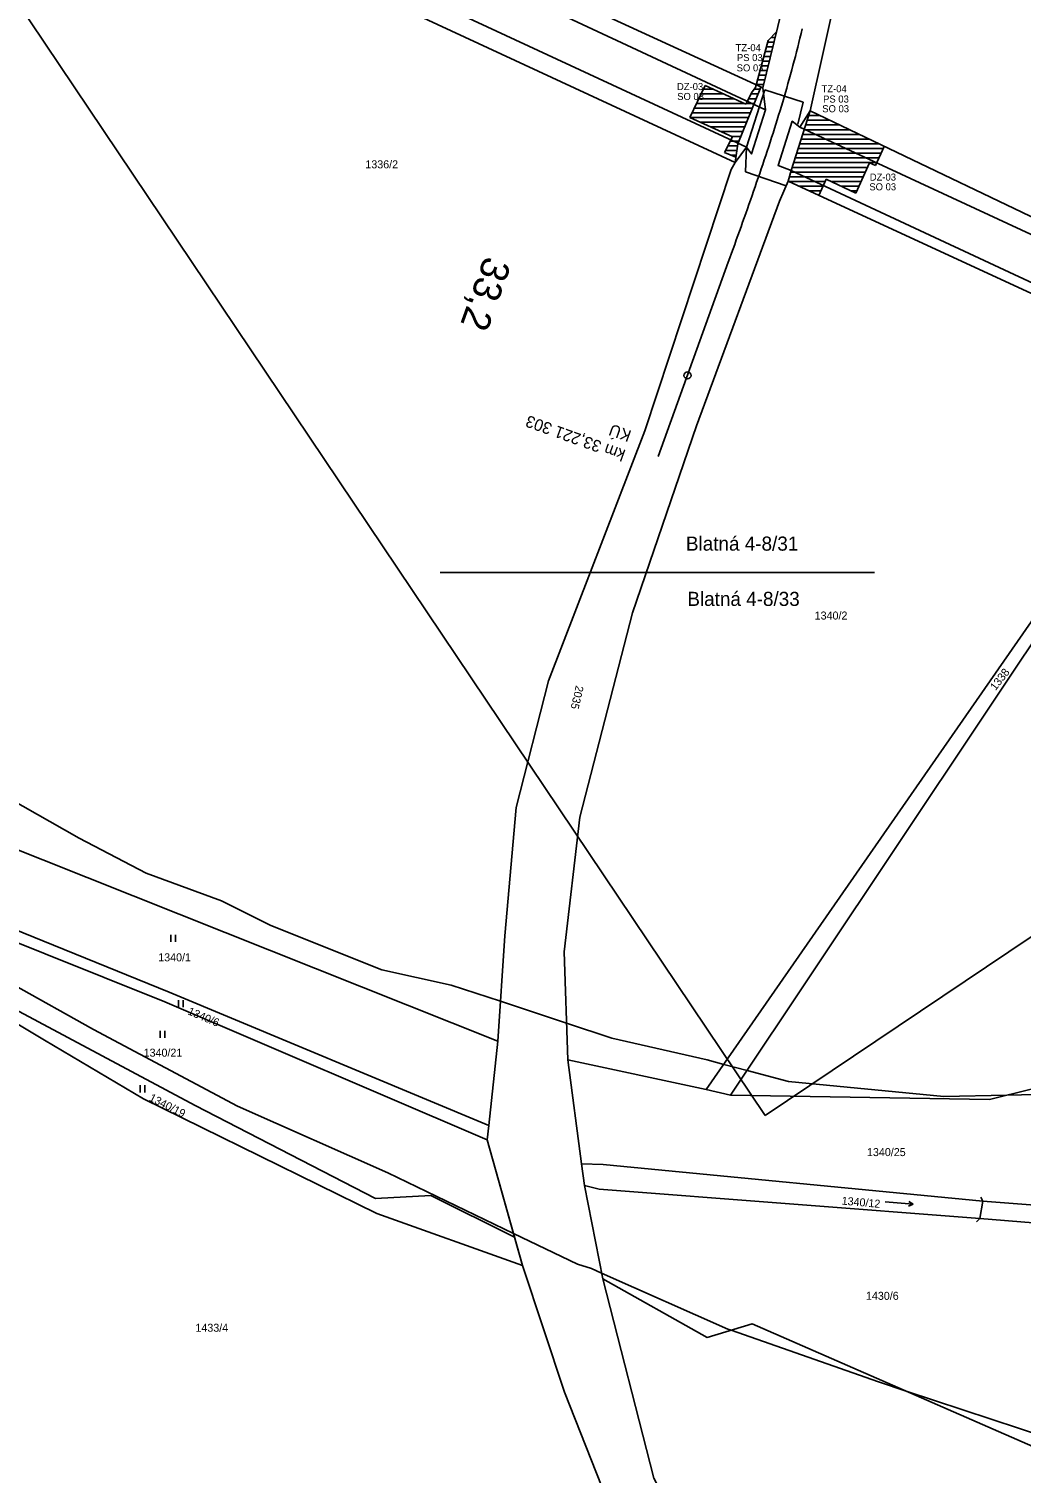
# Model space of a CAD drawing. Extents: x -794765 to -785424, y -1118958 to -1108731.
# Drawn here: x -787414.2 to -787203.5, y -1117691.3 to -1117384.5 of the extents above; entities that cross this region are included whole.
import ezdxf

# ---------------------------------------------------------------- set-up
doc = ezdxf.new("R2010")
doc.units = 0
for name, color, linetype in [('Level 66', 7, 'Continuous'), ('Level 71', 7, 'Continuous'), ('Level 73', 7, 'Continuous'), ('Level 75', 7, 'Continuous'), ('Level 76', 7, 'Continuous'), ('Level 77', 7, 'Continuous'), ('Level 81', 7, 'Continuous'), ('Vrstva 1', 7, 'Continuous'), ('Vrstva 53', 7, 'Continuous')]:
    doc.layers.add(name, color=color, linetype=linetype)

msp = doc.modelspace()

# ---------------------------------------------------------------- linework, layer by layer
at = {"layer": 'Level 66'}
for p, q in [((-787384.07, -1117578.45), (-787384.07, -1117576.95)), ((-787383.07, -1117578.45), (-787383.07, -1117576.95)), ((-787382.44, -1117592.34), (-787382.44, -1117590.84)), ((-787381.44, -1117592.34), (-787381.44, -1117590.84)), ((-787386.34, -1117598.85), (-787386.34, -1117597.35)), ((-787385.34, -1117598.85), (-787385.34, -1117597.35)), ((-787390.57, -1117610.42), (-787390.57, -1117608.92)), ((-787389.57, -1117610.42), (-787389.57, -1117608.92)), ((-787232.37, -1117633.68), (-787226.4, -1117634.2)), ((-787226.4, -1117634.2), (-787227.33, -1117633.62)), ((-787226.4, -1117634.2), (-787227.41, -1117634.62))]:
    msp.add_line(p, q, dxfattribs=at)
at = {"layer": 'Level 71'}
msp.add_line((-787257.85, -1117615.31), (-787008.17, -1117447.61), dxfattribs=at)
msp.add_lwpolyline([(-787008.17, -1117447.61), (-787479.8, -1116745.45), (-787729.47, -1116913.15), (-787257.85, -1117615.31)], dxfattribs=at)
at = {"layer": 'Level 75'}
for p, q in [((-787258.37, -1117397.06), (-787413.22, -1117325.67)), ((-787264.26, -1117412.91), (-787413.04, -1117343.78)), ((-787438.47, -1117550.22), (-787314.62, -1117599.54)), ((-787316.54, -1117617.47), (-787314.62, -1117599.54)), ((-787299.73, -1117603.52), (-787270.37, -1117609.83)), ((-787296.84, -1117625.58), (-787299.73, -1117603.52)), ((-787270.37, -1117609.83), (-787265.2, -1117611.01)), ((-787316.9, -1117620.47), (-787316.54, -1117617.47)), ((-787316.9, -1117620.47), (-787311.06, -1117641.19)), ((-787296.23, -1117630.19), (-787296.84, -1117625.58)), ((-787292.35, -1117650.03), (-787296.23, -1117630.19)), ((-787311.06, -1117641.19), (-787309.36, -1117647.22))]:
    msp.add_line(p, q, dxfattribs=at)
for points in [[(-787248.32, -1117401.92), (-787242.61, -1117376.43), (-787241.48, -1117360.62), (-787238.86, -1117328.3), (-787240.18, -1117309.09), (-787244.19, -1117287.3), (-787255.58, -1117252.15), (-787259.63, -1117245.84), (-787277.47, -1117212.02), (-787300.85, -1117181.82), (-787327.03, -1117156.98), (-787352.43, -1117134.69)], [(-787356.33, -1117146.67), (-787322.75, -1117175.25), (-787307.2, -1117190.47), (-787292.44, -1117206.89), (-787276.75, -1117230.94), (-787266.99, -1117249.13), (-787259.39, -1117269.6), (-787255.71, -1117285.12), (-787252.03, -1117308.63), (-787250.41, -1117335.48), (-787250.96, -1117360.68), (-787254.36, -1117380.85), (-787258.37, -1117397.06)], [(-787264.26, -1117412.91), (-787261.83, -1117409.67), (-787260.78, -1117411.06), (-787257.76, -1117401.7), (-787258.37, -1117397.06)], [(-787248.32, -1117401.92), (-787250.51, -1117405.41), (-787252.11, -1117404.13), (-787255.1, -1117413.5), (-787252.33, -1117414.61), (-787252.97, -1117416.89)], [(-786706.11, -1117656.27), (-786875.36, -1117577.21), (-787053.8, -1117493.01), (-787183.24, -1117433.1), (-787248.32, -1117401.92)], [(-787314.62, -1117599.54), (-787313.18, -1117577.14), (-787310.72, -1117549.93), (-787303.89, -1117523.03), (-787283.43, -1117469.91), (-787265.1, -1117414.39), (-787264.26, -1117412.91)], [(-787252.97, -1117416.89), (-787254.84, -1117421.14), (-787272.47, -1117468.81), (-787286.03, -1117508.52), (-787297.19, -1117551.99), (-787300.57, -1117580.56), (-787299.73, -1117603.52)], [(-787181.08, -1117450.22), (-787189.33, -1117446.27), (-787252.97, -1117416.89)], [(-787270.37, -1117609.83), (-787195.54, -1117502.09), (-787181.08, -1117450.22)], [(-787265.2, -1117611.01), (-787193.72, -1117503.85), (-787178.49, -1117451.46)], [(-787460.09, -1117558.43), (-787384.46, -1117589.14), (-787316.54, -1117617.47)], [(-787462, -1117560.43), (-787385.34, -1117591.22), (-787316.9, -1117620.47)], [(-787311.06, -1117641.19), (-787328.89, -1117632.33), (-787340.58, -1117632.95), (-787378.91, -1117613.22), (-787459.04, -1117570.42)], [(-787459.04, -1117570.42), (-787410.93, -1117599.34), (-787389.9, -1117611.79), (-787340.35, -1117636.15), (-787309.36, -1117647.22)], [(-787265.2, -1117611.01), (-787210.23, -1117611.92), (-787173.69, -1117602.87)], [(-787181.14, -1117636.92), (-787190.01, -1117635.11), (-787200.57, -1117634.38), (-787211.61, -1117633.55), (-787292.23, -1117625.71), (-787296.84, -1117625.58)], [(-787296.23, -1117630.19), (-787293.12, -1117630.97), (-787212.29, -1117637.24), (-787200.96, -1117638.15), (-787190.55, -1117639.98), (-787182.24, -1117641.97)], [(-787309.36, -1117647.22), (-787300.47, -1117674.13), (-787291.42, -1117697.04), (-787259.05, -1117754.75), (-787242.15, -1117783.25)], [(-787192.6, -1117689.33), (-787260.59, -1117659.56), (-787270.16, -1117662.49), (-787292.35, -1117650.03)], [(-787208.31, -1117817.12), (-787233.24, -1117774.71), (-787264.39, -1117724.76), (-787281.5, -1117692.34), (-787292.35, -1117650.03)]]:
    msp.add_lwpolyline(points, dxfattribs=at)
at = {"layer": 'Level 77'}
for p, q in [((-787464.41, -1117305.26), (-787257.76, -1117401.7)), ((-787261.83, -1117409.67), (-787410.13, -1117340.66)), ((-787250.51, -1117405.41), (-787184.71, -1117435.94)), ((-787188.65, -1117444.27), (-787252.33, -1117414.61)), ((-787212.29, -1117637.24), (-787211.61, -1117633.55)), ((-787212.06, -1117632.66), (-787211.61, -1117633.55)), ((-787213, -1117637.95), (-787212.29, -1117637.24))]:
    msp.add_line(p, q, dxfattribs=at)
at = {"layer": 'Level 81'}
for points in [[(-787191.1, -1117610.63), (-787206.5, -1117611), (-787219.92, -1117611.31), (-787252.91, -1117608.11), (-787261.71, -1117605.78), (-787266.65, -1117604.47), (-787270.19, -1117603.53), (-787290.43, -1117598.89), (-787300.02, -1117595.72), (-787314.08, -1117591.07), (-787324.53, -1117587.62), (-787339.3, -1117584.36), (-787362.84, -1117575), (-787373.33, -1117569.71), (-787389.32, -1117563.89), (-787403.58, -1117556.41), (-787433.76, -1117539.31), (-787444.38, -1117525.57), (-787452.36, -1117515.25), (-787457.68, -1117504.99), (-787461.95, -1117499.22), (-787461.95, -1117499.22)], [(-787417.72, -1117587.42), (-787400.54, -1117597.07), (-787369.92, -1117613.34), (-787338, -1117627.53), (-787311.28, -1117640.41), (-787297.7, -1117646.95), (-787294.75, -1117647.86), (-787292.59, -1117648.82), (-787265.76, -1117660.71), (-787265.1, -1117660.94), (-787233.78, -1117671.93), (-787227.93, -1117673.86), (-787191.82, -1117685.76), (-787190, -1117686.35), (-787180.34, -1117690.78), (-787169.78, -1117695.08)]]:
    msp.add_lwpolyline(points, dxfattribs=at)
at = {"layer": 'Vrstva 1'}
for p, q in [((-787255.42, -1117385.12), (-787257.23, -1117386.98)), ((-787255.63, -1117385.34), (-787255.47, -1117385.34)), ((-787257.23, -1117386.98), (-787259.93, -1117396.93)), ((-787257.6, -1117388.34), (-787256.21, -1117388.34)), ((-787257.33, -1117387.34), (-787255.96, -1117387.34)), ((-787256.6, -1117386.34), (-787255.72, -1117386.34)), ((-787258.41, -1117391.34), (-787256.95, -1117391.34)), ((-787258.14, -1117390.34), (-787256.71, -1117390.34)), ((-787257.87, -1117389.34), (-787256.46, -1117389.34)), ((-787259.23, -1117394.34), (-787257.7, -1117394.34)), ((-787258.95, -1117393.34), (-787257.45, -1117393.34)), ((-787258.68, -1117392.34), (-787257.2, -1117392.34)), ((-787270.59, -1117396.5), (-787273.84, -1117403.34)), ((-787270.98, -1117397.34), (-787268.79, -1117397.34)), ((-787270.59, -1117396.5), (-787261.95, -1117400.53)), ((-787261.83, -1117409.67), (-787257.92, -1117397.49)), ((-787261.83, -1117409.67), (-787257.92, -1117397.49)), ((-787259.93, -1117396.93), (-787260.58, -1117397.91)), ((-787260.2, -1117397.34), (-787258.96, -1117397.34)), ((-787259.77, -1117396.34), (-787258.19, -1117396.34)), ((-787259.5, -1117395.34), (-787257.94, -1117395.34)), ((-787257.76, -1117401.7), (-787258.37, -1117397.06)), ((-787257.92, -1117397.49), (-787249.76, -1117400.11)), ((-787257.92, -1117397.49), (-787249.76, -1117400.11)), ((-787272.41, -1117400.34), (-787262.36, -1117400.34)), ((-787271.93, -1117399.34), (-787264.5, -1117399.34)), ((-787271.46, -1117398.34), (-787266.65, -1117398.34)), ((-787260.58, -1117397.91), (-787261.95, -1117400.53)), ((-787261.85, -1117400.34), (-787260.17, -1117400.34)), ((-787261.33, -1117399.34), (-787259.77, -1117399.34)), ((-787260.8, -1117398.34), (-787259.36, -1117398.34)), ((-787249.76, -1117400.11), (-787250.89, -1117404.74)), ((-787249.76, -1117400.11), (-787250.89, -1117404.74)), ((-787273.84, -1117403.34), (-787264.78, -1117407.46)), ((-787273.84, -1117403.34), (-787261.38, -1117403.34)), ((-787273.36, -1117402.34), (-787260.98, -1117402.34)), ((-787272.89, -1117401.34), (-787260.58, -1117401.34)), ((-787248.32, -1117401.92), (-787252.33, -1117414.61)), ((-787248.63, -1117402.92), (-787246.23, -1117402.92)), ((-787271.64, -1117404.34), (-787261.79, -1117404.34)), ((-787269.44, -1117405.34), (-787262.19, -1117405.34)), ((-787267.24, -1117406.34), (-787262.6, -1117406.34)), ((-787249.56, -1117405.92), (-787239.97, -1117405.92)), ((-787249.25, -1117404.92), (-787242.06, -1117404.92)), ((-787248.94, -1117403.92), (-787244.15, -1117403.92)), ((-787264.78, -1117407.46), (-787266.5, -1117410.74)), ((-787265.76, -1117409.34), (-787263.71, -1117409.34)), ((-787265.24, -1117408.34), (-787263.4, -1117408.34)), ((-787265.04, -1117407.34), (-787263, -1117407.34)), ((-787262, -1117414.84), (-787261.83, -1117409.67)), ((-787262, -1117414.84), (-787261.83, -1117409.67)), ((-787250.49, -1117408.92), (-787233.71, -1117408.92)), ((-787250.18, -1117407.92), (-787235.8, -1117407.92)), ((-787249.87, -1117406.92), (-787237.88, -1117406.92)), ((-787234.39, -1117413.52), (-787232.58, -1117409.46)), ((-787266.5, -1117410.74), (-787264.09, -1117411.76)), ((-787266.29, -1117410.34), (-787263.87, -1117410.34)), ((-787265.09, -1117411.34), (-787264.02, -1117411.34)), ((-787254.68, -1117412.21), (-787254.68, -1117412.18)), ((-787251.74, -1117412.92), (-787234.12, -1117412.92)), ((-787251.43, -1117411.92), (-787233.68, -1117411.92)), ((-787251.12, -1117410.92), (-787233.23, -1117410.92)), ((-787250.8, -1117409.92), (-787232.78, -1117409.92)), ((-787238.6, -1117419.4), (-787235.68, -1117412.93)), ((-787235.68, -1117412.93), (-787234.39, -1117413.52)), ((-787253.41, -1117417.88), (-787262, -1117414.84)), ((-787252.67, -1117415.92), (-787237.03, -1117415.92)), ((-787252.36, -1117414.92), (-787236.58, -1117414.92)), ((-787252.05, -1117413.92), (-787236.13, -1117413.92)), ((-787252.9, -1117416.92), (-787245.12, -1117416.92)), ((-787250.74, -1117417.92), (-787245.58, -1117417.92)), ((-787248.57, -1117418.92), (-787246.05, -1117418.92)), ((-787246.49, -1117419.88), (-787244.91, -1117416.46)), ((-787238.6, -1117419.4), (-787244.91, -1117416.46)), ((-787243.93, -1117416.92), (-787237.48, -1117416.92)), ((-787241.78, -1117417.92), (-787237.93, -1117417.92)), ((-787239.63, -1117418.92), (-787238.39, -1117418.92)), ((-787265.68, -1117434.06), (-787280.56, -1117475.36)), ((-787326.9, -1117500), (-787234.64, -1117500))]:
    msp.add_line(p, q, dxfattribs=at)
for points in [[(-787265.68, -1117434.06), (-787265.34, -1117433.12), (-787265, -1117432.18), (-787264.66, -1117431.24), (-787264.32, -1117430.3), (-787263.99, -1117429.35), (-787263.65, -1117428.41), (-787263.31, -1117427.47), (-787262.98, -1117426.53), (-787262.64, -1117425.59), (-787262.3, -1117424.65), (-787261.97, -1117423.7), (-787261.64, -1117422.76), (-787261.3, -1117421.82), (-787260.97, -1117420.87), (-787260.64, -1117419.93), (-787260.31, -1117418.99), (-787259.99, -1117418.04), (-787259.66, -1117417.1), (-787259.33, -1117416.15), (-787259.01, -1117415.2), (-787258.69, -1117414.26), (-787258.37, -1117413.31), (-787258.05, -1117412.36), (-787257.74, -1117411.41), (-787257.42, -1117410.46), (-787257.11, -1117409.51), (-787256.8, -1117408.56), (-787256.49, -1117407.61), (-787256.19, -1117406.66), (-787255.89, -1117405.7), (-787255.58, -1117404.75), (-787255.29, -1117403.8), (-787254.99, -1117402.84), (-787254.7, -1117401.88), (-787254.41, -1117400.93), (-787254.12, -1117399.97), (-787253.84, -1117399.01), (-787253.56, -1117398.05), (-787253.28, -1117397.09), (-787253.01, -1117396.13), (-787252.74, -1117395.16), (-787252.47, -1117394.2), (-787252.21, -1117393.24), (-787251.95, -1117392.27), (-787251.69, -1117391.3), (-787251.44, -1117390.34), (-787251.19, -1117389.37), (-787250.95, -1117388.4), (-787250.71, -1117387.43), (-787250.47, -1117386.46), (-787250.24, -1117385.48), (-787250.01, -1117384.51)], [(-787264.26, -1117412.91), (-787261.83, -1117409.67), (-787260.78, -1117411.06), (-787257.76, -1117401.7), (-787258.37, -1117397.06)]]:
    msp.add_lwpolyline(points, dxfattribs=at)
for points in [[(-787264.26, -1117412.91), (-787263.65, -1117408.95), (-787258.77, -1117396.88), (-787258.37, -1117397.06), (-787257.76, -1117401.7), (-787260.78, -1117411.06), (-787261.83, -1117409.67)], [(-787248.32, -1117401.92), (-787252.33, -1117414.61), (-787255.1, -1117413.5), (-787252.11, -1117404.13), (-787250.51, -1117405.41)]]:
    msp.add_lwpolyline(points, close=True, dxfattribs=at)
msp.add_circle((-787274.35, -1117458.12), 0.75, dxfattribs=at)
at = {"layer": 'Vrstva 53'}
for points in [[(-787458.26, -1117042.74), (-787398.26, -1117093.36), (-787375.17, -1117114.73), (-787356.91, -1117130.76), (-787352.43, -1117134.69), (-787327.03, -1117156.98), (-787300.85, -1117181.82), (-787277.47, -1117212.02), (-787259.63, -1117245.84), (-787255.58, -1117252.15), (-787244.19, -1117287.3), (-787240.18, -1117309.09), (-787238.86, -1117328.3), (-787241.48, -1117360.62), (-787242.61, -1117376.43), (-787248.32, -1117401.92), (-787250.51, -1117405.41), (-787252.11, -1117404.13), (-787255.1, -1117413.5), (-787252.33, -1117414.61), (-787252.97, -1117416.89), (-787254.84, -1117421.14), (-787272.47, -1117468.81)], [(-787283.43, -1117469.91), (-787265.1, -1117414.39), (-787264.26, -1117412.91), (-787261.83, -1117409.67), (-787260.78, -1117411.06), (-787257.76, -1117401.7), (-787258.37, -1117397.06), (-787254.36, -1117380.85), (-787250.96, -1117360.68), (-787250.41, -1117335.48), (-787252.03, -1117308.63), (-787255.71, -1117285.12), (-787259.39, -1117269.6), (-787266.99, -1117249.13), (-787276.75, -1117230.94), (-787292.44, -1117206.89), (-787307.2, -1117190.47), (-787322.75, -1117175.25), (-787356.33, -1117146.67), (-787360.49, -1117143.13), (-787390.97, -1117117.19), (-787466.48, -1117052.03)], [(-787145.72, -1117945.71), (-787157.56, -1117922.69), (-787175.04, -1117894.4), (-787191.61, -1117867.54), (-787217.39, -1117821.69), (-787221.52, -1117814.46), (-787228.62, -1117803.68), (-787238.02, -1117789.4), (-787242.15, -1117783.25), (-787259.05, -1117754.75), (-787291.42, -1117697.04), (-787300.47, -1117674.13), (-787309.36, -1117647.22), (-787316.9, -1117620.47), (-787316.54, -1117617.47), (-787314.62, -1117599.54), (-787313.18, -1117577.14), (-787310.72, -1117549.93), (-787303.89, -1117523.03), (-787283.43, -1117469.91)], [(-787272.47, -1117468.81), (-787286.03, -1117508.52), (-787297.19, -1117551.99), (-787300.57, -1117580.56), (-787299.73, -1117603.52), (-787296.84, -1117625.58), (-787296.23, -1117630.19), (-787292.35, -1117650.03), (-787281.5, -1117692.34), (-787264.39, -1117724.76), (-787233.24, -1117774.71), (-787208.31, -1117817.12), (-787200.76, -1117830.15), (-787163.99, -1117893.46), (-787154.27, -1117910.76), (-787140.05, -1117937.14), (-787131.85, -1117955.61)]]:
    msp.add_lwpolyline(points, dxfattribs=at)

# ---------------------------------------------------------------- texts
at = {"layer": 'Level 73'}
msp.add_text('33,2', height=6, rotation=250.1954, dxfattribs=at).set_placement((-787317.37, -1117432.52))
at = {"layer": 'Level 76'}
for s, p in [('1336/2', (-787342.77, -1117414.13)), ('1340/2', (-787247.34, -1117509.98)), ('1340/1', (-787386.76, -1117582.59)), ('1340/21', (-787389.86, -1117602.84)), ('1340/25', (-787236.23, -1117623.96)), ('1430/6', (-787236.45, -1117654.49)), ('1433/4', (-787378.86, -1117661.27))]:
    msp.add_text(s, height=1.7, dxfattribs=at).set_placement(p)
for s, rotation, p in [('1338', 52, (-787208.93, -1117525.18)), ('2035', 257, (-787298.04, -1117523.88)), ('1340/6', 337, (-787380.64, -1117593.8)), ('1340/19', 333, (-787388.85, -1117612.1)), ('1340/12', 355, (-787241.66, -1117634.25))]:
    msp.add_text(s, height=1.7, rotation=rotation, dxfattribs=at).set_placement(p)
at = {"layer": 'Vrstva 1'}
for s, height, p in [('TZ-04', 1.5, (-787264.13, -1117389.25)), ('PS 03', 1.5, (-787263.85, -1117391.35)), ('SO 03', 1.5, (-787263.9, -1117393.54)), ('DZ-03', 1.5, (-787276.59, -1117397.51)), ('TZ-04', 1.5, (-787245.88, -1117397.97)), ('SO 03', 1.5, (-787276.54, -1117399.61)), ('SO 03', 1.5, (-787245.73, -1117402.22)), ('PS 03', 1.5, (-787245.55, -1117400.16)), ('DZ-03', 1.5, (-787235.64, -1117416.74)), ('SO 03', 1.5, (-787235.73, -1117418.8)), ('Blatná 4-8/31', 3, (-787274.68, -1117495.35)), ('Blatná 4-8/33', 3, (-787274.38, -1117507.09))]:
    msp.add_text(s, height=height, dxfattribs=at).set_placement(p)
for s, rotation, p in [('km 33,221 303', 160.1889, (-787287.33, -1117474.04)), ('KÚ', 160.1888, (-787286.07, -1117469.95))]:
    msp.add_text(s, height=2.5, rotation=rotation, dxfattribs=at).set_placement(p)

doc.saveas('drawing.dxf')
